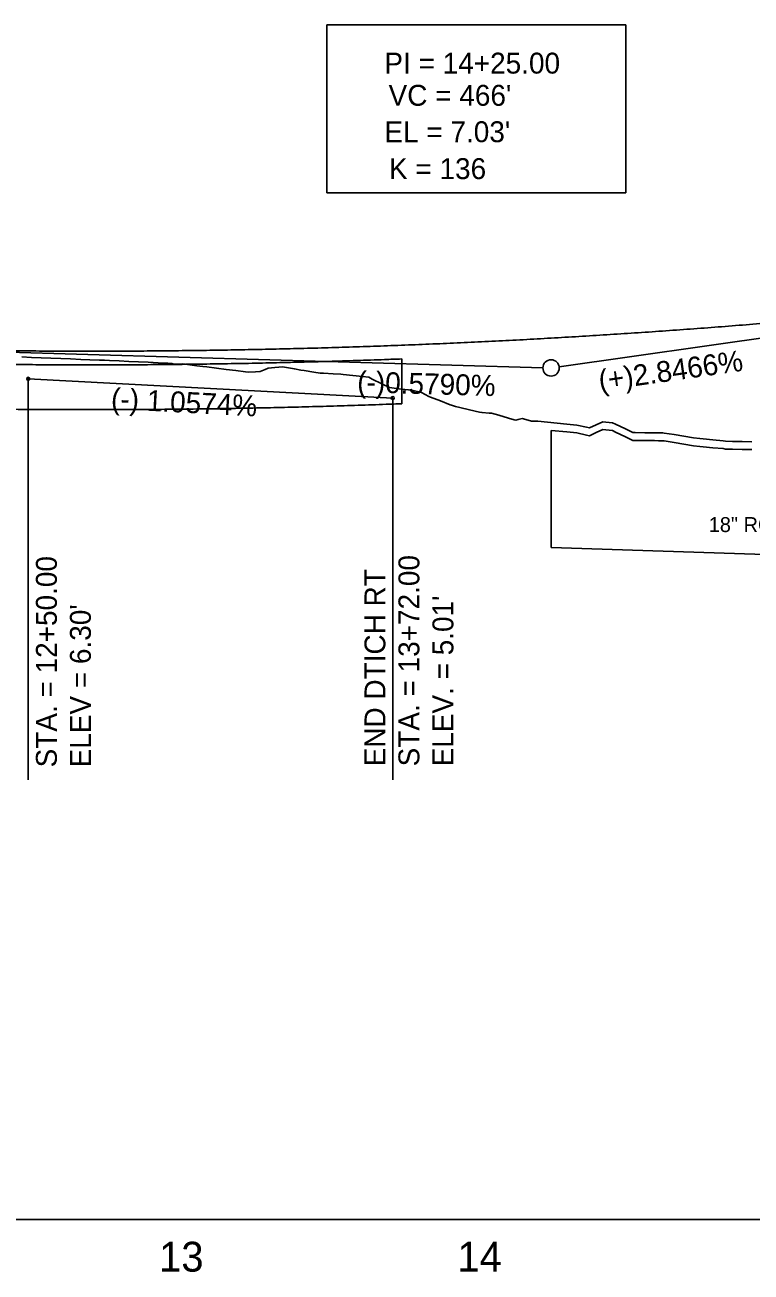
# Model space of a CAD drawing. Extents: x 1626634 to 1638383, y 876896 to 886347.
# Drawn here: x 1632962.8 to 1633205.8, y 884030 to 884447.6 of the extents above; entities that cross this region are included whole.
import ezdxf

# ---------------------------------------------------------------- set-up
doc = ezdxf.new("R2010")
doc.units = 0
for name, color, linetype in [('Exist Profile Cell', 7, 'Continuous'), ('Exist Vertical Profile Ground Line', 7, 'Continuous'), ('Exist Vertical Profile Horizontal Axis Label Major', 7, 'Continuous'), ('Old_Level_1', 7, 'Continuous'), ('Prop Vertical Profile Curve Label', 7, 'Continuous'), ('Prop Vertical Profile Grade', 7, 'Continuous'), ('Prop Vertical Profile Grade Label', 7, 'Continuous'), ('Prop VPI Label', 7, 'Continuous'), ('Scratch_Level_3', 7, 'Continuous'), ('Sheet Data Field CELL', 7, 'Continuous'), ('Sheet Plan And Profile CELL', 7, 'Continuous'), ('Sheet Profile CELL', 7, 'Continuous')]:
    doc.layers.add(name, color=color, linetype=linetype)

msp = doc.modelspace()

# ---------------------------------------------------------------- linework, layer by layer
at = {"layer": 'Exist Profile Cell'}
msp.add_line((1632713.86, 884047.61), (1634948.96, 884047.61), dxfattribs=at)
at = {"layer": 'Exist Vertical Profile Ground Line'}
msp.add_lwpolyline([(1632961.7, 884336.41), (1632964.96, 884336.28), (1632968.22, 884336.15), (1632971.48, 884336.01), (1632974.74, 884335.88), (1632977.99, 884335.74), (1632981.42, 884335.59), (1632984.51, 884335.48), (1632987.77, 884335.36), (1632989.4, 884335.3), (1632991.03, 884335.22), (1632994.29, 884335.08), (1632997.54, 884334.93), (1633000.8, 884334.78), (1633004.06, 884334.63), (1633007.32, 884334.48), (1633010.58, 884334.33), (1633011.95, 884334.27), (1633012.76, 884333.97), (1633014.05, 884334.02), (1633015.37, 884334.08), (1633016.06, 884334.05), (1633016.43, 884333.99), (1633017.22, 884333.85), (1633020.35, 884333.48), (1633022.27, 884333.24), (1633023.61, 884333.08), (1633026.87, 884332.67), (1633030.13, 884332.26), (1633033.39, 884331.84), (1633036.64, 884331.43), (1633037.74, 884331.29), (1633039.9, 884331.45), (1633041.55, 884331.57), (1633043.16, 884332.27), (1633044.15, 884332.7), (1633046.42, 884332.88), (1633049.11, 884333.09), (1633049.68, 884332.99), (1633052.94, 884332.42), (1633055.08, 884332.05), (1633056.19, 884331.87), (1633059.45, 884331.36), (1633061.53, 884331.03), (1633062.71, 884330.97), (1633065.97, 884330.79), (1633068.44, 884330.65), (1633069.23, 884330.57), (1633072.49, 884330.2), (1633075.74, 884329.84), (1633077.86, 884329.6), (1633079, 884329.03), (1633082.26, 884327.39), (1633084.74, 884326.14), (1633085.52, 884326.05), (1633088.78, 884325.67), (1633092.3, 884325.26), (1633095.5, 884324.57), (1633097.97, 884323.17), (1633098.55, 884322.95), (1633101.81, 884321.68), (1633105.07, 884320.4), (1633105.51, 884320.23), (1633106.82, 884319.88), (1633108.33, 884319.5), (1633111.59, 884318.68), (1633114.85, 884317.97), (1633115.77, 884317.77), (1633118.1, 884317.63), (1633118.94, 884317.57), (1633121.36, 884316.89), (1633124.62, 884315.97), (1633126.49, 884315.38), (1633127.1, 884315.26), (1633127.88, 884315.47), (1633129.23, 884315.83), (1633131.14, 884315.23), (1633132.27, 884314.87), (1633133.93, 884314.94), (1633134.4, 884314.89), (1633137.65, 884314.58), (1633140.91, 884314.26), (1633144.17, 884313.95), (1633147.43, 884313.59), (1633150.69, 884312.9), (1633151.68, 884312.69), (1633153.95, 884313.72), (1633156.17, 884314.72), (1633157.2, 884314.62), (1633159.45, 884314.41), (1633160.46, 884313.92), (1633163.72, 884312.32), (1633166.24, 884311.09), (1633166.98, 884311.08), (1633170.24, 884311.06), (1633173.5, 884311.03), (1633174.84, 884311.02), (1633176.31, 884311.01), (1633176.75, 884310.94), (1633180.01, 884310.4), (1633183.27, 884309.86), (1633186.53, 884309.35), (1633188.67, 884309.07), (1633189.79, 884308.97), (1633193.05, 884308.68), (1633196.41, 884308.38), (1633197.25, 884308.18), (1633199.56, 884308.15), (1633202.82, 884308.09), (1633206.08, 884308.04)], dxfattribs=at)
at = {"layer": 'Old_Level_1'}
for p, q in [((1632963.86, 884329.11), (1632963.86, 884194.83)), ((1633085.86, 884322.66), (1633085.86, 884194.83))]:
    msp.add_line(p, q, dxfattribs=at)
for centre in [(1632963.86, 884329.11), (1633085.86, 884322.66)]:
    msp.add_circle(centre, 0.5, dxfattribs=at)
at = {"layer": 'Prop Vertical Profile Grade'}
msp.add_spline([(1632905.86, 884339.49), (1632915.18, 884339.24), (1632924.5, 884339.02), (1632933.82, 884338.83), (1632943.14, 884338.67), (1632952.46, 884338.54), (1632961.78, 884338.45), (1632971.1, 884338.39), (1632980.42, 884338.36), (1632989.74, 884338.36), (1632999.06, 884338.39), (1633008.38, 884338.46), (1633017.7, 884338.56), (1633027.02, 884338.68), (1633036.34, 884338.85), (1633045.66, 884339.04), (1633054.98, 884339.26), (1633064.3, 884339.52), (1633073.62, 884339.81), (1633082.94, 884340.13), (1633092.26, 884340.48), (1633101.58, 884340.87), (1633110.9, 884341.28), (1633120.22, 884341.73), (1633129.54, 884342.21), (1633138.86, 884342.73), (1633148.18, 884343.27), (1633157.5, 884343.85), (1633166.82, 884344.45), (1633176.14, 884345.09), (1633185.46, 884345.77), (1633194.78, 884346.47), (1633204.1, 884347.21), (1633213.42, 884347.97), (1633222.74, 884348.77), (1633232.06, 884349.61), (1633241.38, 884350.47), (1633250.7, 884351.36), (1633260.02, 884352.29), (1633269.34, 884353.25), (1633278.66, 884354.24), (1633287.98, 884355.27), (1633297.3, 884356.32), (1633306.62, 884357.41), (1633315.94, 884358.53), (1633325.26, 884359.68), (1633334.58, 884360.86), (1633343.9, 884362.08), (1633353.22, 884363.32), (1633362.54, 884364.6), (1633371.86, 884365.91)], degree=3, dxfattribs=at)
at = {"layer": 'Prop VPI Label'}
for p, q in [((1633371.86, 884365.91), (1633141.59, 884333.14)), ((1632905.86, 884339.49), (1633136.11, 884332.83))]:
    msp.add_line(p, q, dxfattribs=at)
msp.add_lwpolyline([(1633063.86, 884447.61), (1633163.86, 884447.61), (1633163.86, 884391.43), (1633063.86, 884391.43)], close=True, dxfattribs=at)
msp.add_lwpolyline([(1633063.86, 884447.61), (1633163.86, 884447.61), (1633163.86, 884391.43), (1633063.86, 884391.43)], close=True, dxfattribs=at)
msp.add_circle((1633138.86, 884332.75), 2.75, dxfattribs=at)
at = {"layer": 'Scratch_Level_3'}
for p, q in [((1633088.86, 884335.76), (1633088.86, 884320.75)), ((1633138.86, 884311.82), (1633138.86, 884272.61)), ((1633138.86, 884272.61), (1633213.86, 884270.11))]:
    msp.add_line(p, q, dxfattribs=at)
msp.add_lwpolyline([(1633138.86, 884311.82), (1633144.17, 884311.31), (1633147.43, 884310.96), (1633150.69, 884310.26), (1633151.68, 884310.05), (1633153.95, 884311.08), (1633156.17, 884312.08), (1633157.2, 884311.98), (1633159.45, 884311.77), (1633160.46, 884311.28), (1633163.72, 884309.68), (1633166.24, 884308.45), (1633166.98, 884308.44), (1633170.24, 884308.42), (1633173.5, 884308.39), (1633174.84, 884308.38), (1633176.31, 884308.37), (1633176.75, 884308.3), (1633180.01, 884307.76), (1633183.27, 884307.22), (1633186.53, 884306.71), (1633188.67, 884306.43), (1633189.79, 884306.33), (1633193.05, 884306.04), (1633196.41, 884305.74), (1633197.25, 884305.54), (1633199.56, 884305.51), (1633202.82, 884305.45), (1633206.08, 884305.4)], dxfattribs=at)
for points in [[(1632938.86, 884334.16), (1632943.07, 884334.09), (1632952.41, 884333.96), (1632961.74, 884333.87), (1632971.08, 884333.8), (1632980.42, 884333.77), (1632989.75, 884333.78), (1632999.09, 884333.81), (1633008.42, 884333.87), (1633017.76, 884333.97), (1633027.09, 884334.1), (1633036.43, 884334.26), (1633045.77, 884334.46), (1633055.1, 884334.68), (1633064.44, 884334.94), (1633073.77, 884335.23), (1633083.11, 884335.55), (1633088.86, 884335.76)], [(1633088.86, 884320.75), (1633083.65, 884320.56), (1633074.26, 884320.24), (1633064.88, 884319.95), (1633055.49, 884319.69), (1633046.1, 884319.46), (1633036.72, 884319.27), (1633027.33, 884319.1), (1633017.94, 884318.97), (1633008.55, 884318.88), (1632999.17, 884318.81), (1632989.78, 884318.78), (1632980.39, 884318.77), (1632971.01, 884318.8), (1632961.62, 884318.87), (1632952.23, 884318.96), (1632942.84, 884319.09), (1632938.86, 884319.15)]]:
    msp.add_spline(points, degree=3, dxfattribs=at)
at = {"layer": 'Sheet Plan And Profile CELL'}
msp.add_line((1632963.86, 884329.11), (1633085.86, 884322.66), dxfattribs=at)

# ---------------------------------------------------------------- texts
at = {"layer": 'Exist Vertical Profile Horizontal Axis Label Major'}
for s, p in [('13', (1633007.67, 884030.11)), ('14', (1633107.51, 884030.11))]:
    msp.add_text(s, height=10, dxfattribs=at).set_placement(p)
at = {"layer": 'Old_Level_1'}
for s, p in [('STA. = 12+50.00', (1632973.45, 884198.97)), ('STA. = 13+72.00', (1633094.78, 884199.31)), ('END DTICH RT', (1633083.41, 884199.31)), ("ELEV = 6.30'", (1632984.83, 884198.97)), ("ELEV. = 5.01'", (1633106.16, 884199.31))]:
    msp.add_text(s, height=7, rotation=90, dxfattribs=at).set_placement(p)
at = {"layer": 'Prop Vertical Profile Curve Label'}
for s, p in [("VC = 466'", (1633084.47, 884420.54)), ('K = 136', (1633084.6, 884395.98))]:
    msp.add_text(s, height=7, dxfattribs=at).set_placement(p)
at = {"layer": 'Prop Vertical Profile Grade Label'}
for s, rotation, p in [('(+)2.8466%', 8.1004, (1633155.27, 884324.98)), ('(-)0.5790%', 358.3417, (1633073.91, 884324.63))]:
    msp.add_text(s, height=7, rotation=rotation, dxfattribs=at).set_placement(p)
at = {"layer": 'Prop VPI Label'}
for s, p in [('PI = 14+25.00', (1633083.06, 884431.32)), ("EL = 7.03'", (1633083.06, 884408.34))]:
    msp.add_text(s, height=7, dxfattribs=at).set_placement(p)
at = {"layer": 'Sheet Data Field CELL'}
msp.add_text('18" RCP-III', height=5, dxfattribs=at).set_placement((1633191.62, 884277.78))
at = {"layer": 'Sheet Profile CELL'}
msp.add_text('(-) 1.0574%', height=7, rotation=356.9737, dxfattribs=at).set_placement((1632991.46, 884319.06))

doc.saveas('drawing.dxf')
